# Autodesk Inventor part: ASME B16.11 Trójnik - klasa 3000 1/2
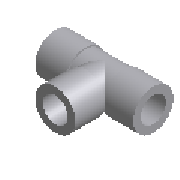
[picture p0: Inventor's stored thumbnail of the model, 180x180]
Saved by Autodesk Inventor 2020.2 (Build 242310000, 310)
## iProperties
Manager: www.cadconsulting.pl
Company: Fabian Stasiak CAD Consulting
Created: 2014-02
Part Number: ASME B16.11 Trójnik - klasa 3000 1/2
Material: Stal
Description: Trójnik kuty, do przyspawania - klasa 3000
Document SubType Name: Modeling
Standard: ASME B16.11
Designer: F.Stasiak
Standard Revision: 2005
Standards Organization: ANSI
Language: pl-PL
Size Designation: 1/2
Categories: <MemberInstance><Categories><Category DisplayName="Rury cienko- i grubościenne" InternalName="4347fa0f-2144-441d-94cd-e3e15c92b736" Mnemonic="TUBEANDPIPE"><Cate
Density: 1 g/cm^3
Appearance: Płyta
Catalog Web Link: www.expertbooks.pl
NAME: PIPING: ASME B16.11 Tee - Class 3000
DATA: <meta><inlinegroups number="1" deflen="4.1656"></inlinegroups><connections number="3"></connections><angles><a>1.57079632679489</a><a>3.14159265358979</a></angl
IsCustomPart: 0
Author: F.Stasiak
Subject: Zbiór ćwiczeń. Autodesk Inventor 2020. Kurs Professional
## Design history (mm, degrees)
sketch "Sketch1"
  geometry: L1 (0, 0)-(25.4, 0); L2 (25.4, 0)-(25.4, 14.319); L3 (13.741, 14.948)-(0, 14.948); L4 (0, 10.858)-(0, 0); L5 (0, 10.858)-(9.652, 10.859); L6 (9.652, 10.859)-(9.652, 7.518); L7 (9.652, 7.518)-(25.4, 7.518); L8 (13.741, 14.948)-(13.741, 14.319); L9 (13.741, 14.319)-(25.4, 14.319); L10 (0, 10.858)-(0, 14.948); L11 (41.148, 7.518)-(25.4, 7.518); L12 (41.148, 10.859)-(41.148, 7.518); L13 (50.8, 10.859)-(41.148, 10.859); L14 (50.8, 10.859)-(50.8, 14.948); L15 (37.059, 14.948)-(50.8, 14.948); L16 (37.059, 14.948)-(37.059, 14.319); L17 (37.059, 14.319)-(25.4, 14.319); L18 (50.8, 10.859)-(50.8, 0); L19 (50.8, 0)-(25.4, 0); L20 (9.652, 7.518)-(9.652, 0); L21 (41.148, 7.518)-(41.148, 0)
  constraints: 42 end point, 8 perpendicular, 7 symmetric about line, 3 point on line, 2 parallel, 1 collinear, 1 horizontal, 9 other
  dimensions: "d0" = 15.0368 diameter of L7 L1 (= D); "d1" = 21.717 diameter of L5 L1 (= B); "d2" = 4.0894 distance between parallel lines of L5 L3 (= C1); "d3" = 9.652 distance between parallel lines of L10 L6 (= J1); "d4" = 15.748 distance between parallel lines of L2 L6 (= A); "d19" = 4.0894 distance between parallel lines of L6 L8 (= C1); "d21" = 6.80085 distance between parallel lines of L7 L9 (= G + 0.75 x C1)
revolve "Revolve1" sketch "Sketch1" stored, may be unused: angle "d8" = 90 deg
sketch "Sketch2"
  geometry: L1 (0, 0)-(-25.4, 0) reference; L2 (-25.4, 0)-(-25.4, 25.4); L3 (-25.4, 25.4)-(-36.258, 25.4); L4 (-40.348, 25.4)-(-40.348, 11.659); L5 (-32.918, 0)-(-25.4, 0); L6 (-36.258, 25.4)-(-36.258, 15.748); L7 (-36.258, 15.748)-(-32.918, 15.748); L8 (-32.918, 15.748)-(-32.918, 0); L9 (-36.258, 25.4)-(-40.348, 25.4); L10 (-40.348, 11.659)-(-39.719, 11.659); L11 (-39.719, 11.659)-(-39.719, 0); L12 (-32.918, 0)-(-39.719, 0); L13 (-32.918, 15.748)-(-25.4, 15.748)
  constraints: 24 end point, 9 perpendicular, 2 parallel, 1 point on line
  dimensions: "d5" = 15.0368 diameter of L8 L2 (= D); "d6" = 21.717 diameter of L6 L2 (= B); "d7" = 4.0894 distance between parallel lines of L6 L4 (= C1); "d9" = 9.652 distance between parallel lines of L7 L9 (= J1); "d10" = 15.748 distance between parallel lines of L7 L5 (= A); "d22" = 4.0894 distance between parallel lines of L7 L10 (= C1); "d26" = 6.80085 distance between parallel lines of L8 L11 (= G + 0.75 x C1)
revolve "Revolve2" sketch "Sketch2" stored, may be unused: angle "d18" = 90 deg
sketch "Sketch3"
  geometry: C1 r 10.858 at (0, 0) reference; 1 further point
  constraints: 1 coincident
hole "Hole1" sketch "Sketch3" at (0, 0) diameter "d11" = 15.0368 (= D); stored, may be unused: countersink angle "d23" = 82 deg, drill point angle "d25" = 118 deg; dims "d12" = 21.717 (= B), "d13" = 9.652 (= J1), "d20" = 12.7, "d24" = 19.05
sketch "Sketch4"
  geometry: C1 r 14.948 at (0, 0) reference; 1 further point
  constraints: 1 coincident
hole "Hole2" sketch "Sketch4" at (0, 0) diameter "d14" = 15.0368 (= D); stored, may be unused: drill point angle "d17" = 118 deg, countersink angle "d30" = 82 deg; dims "d15" = 21.717 (= B), "d16" = 9.652 (= J1), "d27" = 12.7, "d31" = 19.05
sketch "Sketch5"
  geometry: C1 r 14.948 at (0, 0) reference; 1 further point
  constraints: 1 coincident
hole "Hole3" sketch "Sketch5" at (0, 0) diameter "d28" = 15.0368 (= D); stored, may be unused: countersink angle "d41" = 82 deg, drill point angle "d43" = 118 deg; dims "d29" = 21.717 (= B), "d32" = 9.652 (= J1), "d38" = 12.7, "d42" = 19.05
workaxis "Work Axis1"
workpoint "Work Point1"
workpoint "Work Point2"
workaxis "Work Axis2"
workpoint "Work Point3"
workpoint "Work Point4"
workaxis "Work Axis3"
workpoint "Work Point5"
workpoint "Work Point6"
body "Solid1"
other parameters: "B" = 21.717 [user parameter; used in 5 equation terms], "D" = 15.0368 [user parameter; used in 5 equation terms], "C1" = 4.0894 [user parameter; used in 6 equation terms], "G" = 3.7338 [user parameter; used in 2 equation terms], "J1" = 9.652 [user parameter; used in 5 equation terms], "A" = 15.748 [user parameter; used in 2 equation terms], "Size_Designation" = 5 [user parameter]
